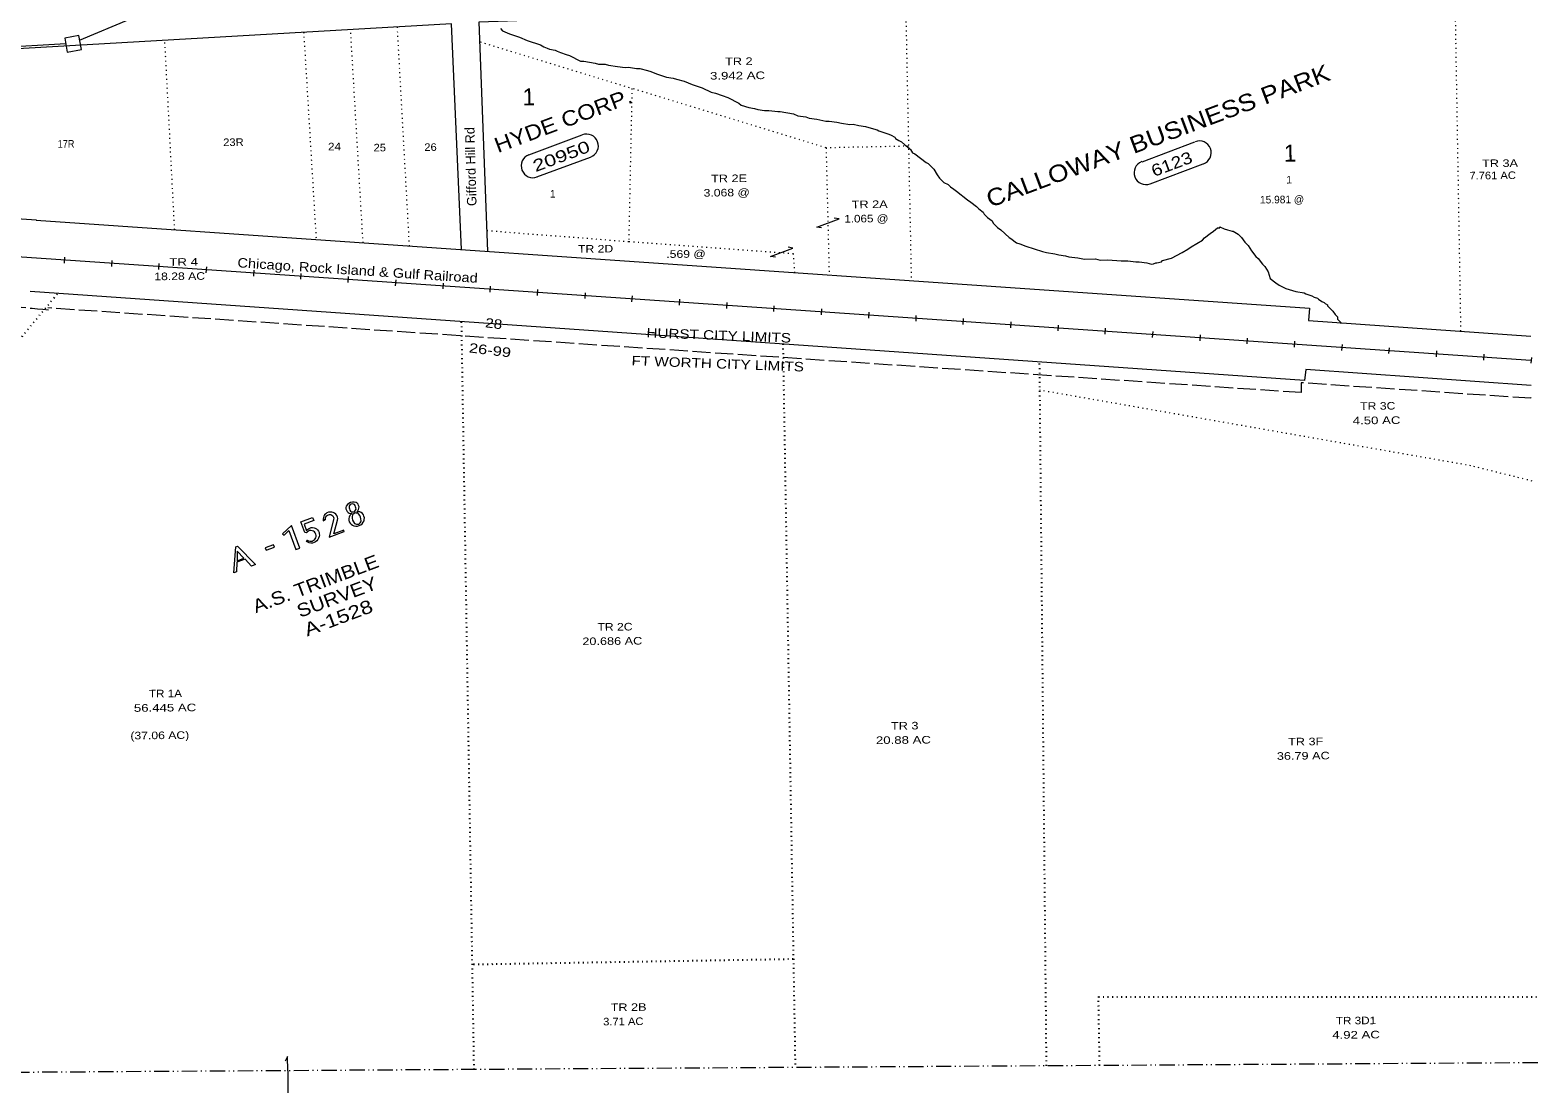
# Model space of a CAD drawing. Extents: x 2356373 to 2371954, y 6966197 to 6989612.
# Drawn here: x 2368762 to 2371940, y 6978330 to 6980551 of the extents above; entities that cross this region are included whole.
import ezdxf

# ---------------------------------------------------------------- set-up
doc = ezdxf.new("R2010")
doc.units = 0
doc.header["$LTSCALE"] = 6.4
for name, pattern in [('DASH_DOUBLE_DOT', [9.2, 5, -1.2, 0.3, -1.2, 0.3, -1.2]), ('DOTTED', [1.5, 0.3, -1.2]), ('LONG_DASHED', [7.5, 6, -1.5])]:
    doc.linetypes.add(name, pattern=pattern)
for name, color, linetype in [('10', 7, 'Continuous'), ('11', 7, 'Continuous'), ('18', 7, 'Continuous'), ('20', 7, 'Continuous'), ('22', 7, 'Continuous'), ('26', 7, 'Continuous')]:
    doc.layers.add(name, color=color, linetype=linetype)
for name, color, linetype, lineweight in [('12', 7, 'Continuous', 13), ('13', 7, 'Continuous', 13), ('15', 7, 'Continuous', 13), ('16', 7, 'DOTTED', 13), ('17', 7, 'Continuous', 13), ('19', 7, 'Continuous', 13), ('27', 7, 'LONG_DASHED', 13), ('30', 7, 'Continuous', 13), ('5', 7, 'DOTTED', 13), ('6', 7, 'DOTTED', 13), ('60', 7, 'DOTTED', 25), ('7', 7, 'Continuous', 13), ('8', 7, 'Continuous', 13)]:
    doc.layers.add(name, color=color, linetype=linetype, lineweight=lineweight)

msp = doc.modelspace()

# ---------------------------------------------------------------- linework, layer by layer
at = {"layer": '13'}
msp.add_line((2369304.625, 6978357.84), (2369305.815, 6978236.683), dxfattribs=at)
for points in [[(2370429.872, 6980134.321), (2370419.857, 6980136.02), (2370466.672, 6980153.577), (2370456.659, 6980155.178)], [(2370332.504, 6980072.581), (2370322.491, 6980074.181), (2370369.306, 6980091.737), (2370359.292, 6980093.437)], [(2369304.625, 6978357.84), (2369304.331, 6978387.728), (2369299.432, 6978377.683)]]:
    msp.add_lwpolyline(points, dxfattribs=at)
at = {"layer": '15', "linetype": 'DASH_DOUBLE_DOT'}
msp.add_line((2371939.757, 6978374.623), (2368123.015, 6978350.331), dxfattribs=at)
at = {"layer": '15'}
for points in [[(2369726.546, 6980084.723), (2369707.796, 6980568.709), (2370225.479, 6980586.991), (2371917.951, 6980594.717)], [(2369670.524, 6980088.572), (2369649.85, 6980564.841), (2367466.67, 6980438.925)], [(2368774.155, 6980150.448), (2371458.259, 6979965.169), (2371456.512, 6979939.357), (2371924.713, 6979906.369)], [(2371925.733, 6979802.406), (2371450.527, 6979836.227), (2371447.758, 6979812.806), (2368761.633, 6980000.365)]]:
    msp.add_lwpolyline(points, dxfattribs=at)
msp.add_arc((2368276.401, 6973930.218), 6240.133, 85.42076, 91.53776, dxfattribs=at)
at = {"layer": '16'}
for p, q in [((2371777.648, 6979916.82), (2371765.999, 6980594.025)), ((2370607.359, 6980588.743), (2370618.914, 6980023.106))]:
    msp.add_line(p, q, dxfattribs=at)
msp.add_lwpolyline([(2369710.211, 6980526.545), (2370030.09, 6980428.314), (2370023.267, 6980105.032), (2369725.121, 6980128.098)], dxfattribs=at)
at = {"layer": '17'}
for p, q in [((2369812.521, 6980288.514), (2369925.077, 6980330.609)), ((2371105.319, 6980273.92), (2371216.876, 6980316.104)), ((2369829.976, 6980241.698), (2369942.534, 6980283.793)), ((2371122.774, 6980227.202), (2371234.331, 6980269.288))]:
    msp.add_line(p, q, dxfattribs=at)
for points in [[(2369465.784, 6979520.022), (2369466.252, 6979523.275), (2369465.22, 6979526.514), (2369464.191, 6979529.503), (2369462.167, 6979532.083), (2369459.646, 6979534.158), (2369456.634, 6979535.577), (2369453.128, 6979536.243), (2369450.129, 6979536.214), (2369452.109, 6979538.182), (2369453.585, 6979540.597), (2369454.557, 6979543.405), (2369455.029, 6979546.309), (2369454.001, 6979549.148), (2369452.977, 6979551.737), (2369450.954, 6979553.916), (2369448.441, 6979555.491), (2369444.433, 6979556.352), (2369440.934, 6979556.268), (2369436.945, 6979555.329), (2369433.463, 6979553.546), (2369430.49, 6979551.016), (2369428.021, 6979547.844), (2369427.049, 6979545.034), (2369427.078, 6979542.036), (2369428.106, 6979539.197), (2369429.631, 6979536.613), (2369431.65, 6979534.533), (2369434.164, 6979533.057), (2369437.169, 6979532.388), (2369440.168, 6979532.467), (2369437.19, 6979530.438), (2369435.216, 6979527.819), (2369433.747, 6979524.756), (2369433.278, 6979521.502), (2369433.311, 6979518.153), (2369434.342, 6979514.914), (2369435.871, 6979511.98), (2369437.895, 6979509.551), (2369440.912, 6979507.68), (2369443.923, 6979506.56), (2369443.923, 6979506.56), (2369447.927, 6979505.799), (2369451.427, 6979505.885), (2369454.917, 6979506.819), (2369458.399, 6979508.502), (2369461.375, 6979510.931), (2369463.844, 6979513.905), (2369465.316, 6979516.818), (2369465.784, 6979520.022)], [(2369448.576, 6979541.747), (2369448.05, 6979544.292), (2369447.527, 6979546.735), (2369446.505, 6979549.024), (2369444.985, 6979551.109), (2369442.973, 6979552.339), (2369440.468, 6979552.764), (2369437.973, 6979552.339), (2369435.986, 6979551.121), (2369434.506, 6979549.206), (2369434.027, 6979546.953), (2369434.053, 6979544.404), (2369434.578, 6979541.96), (2369435.599, 6979539.67), (2369437.119, 6979537.586), (2369439.133, 6979536.205), (2369441.637, 6979535.681), (2369444.132, 6979536.106), (2369446.119, 6979537.425), (2369447.599, 6979539.388), (2369448.576, 6979541.747)], [(2369332.37, 6979514.912), (2369356.773, 6979524.199), (2369359.337, 6979517.527), (2369338.918, 6979509.778), (2369344.052, 6979496.133), (2369346.028, 6979498.501), (2369348.008, 6979500.37), (2369350.994, 6979501.749), (2369353.986, 6979502.578), (2369356.984, 6979502.807), (2369359.987, 6979502.387), (2369362.494, 6979501.412), (2369365.508, 6979499.892), (2369367.529, 6979497.812), (2369369.551, 6979495.383), (2369370.579, 6979492.643), (2369371.107, 6979489.7), (2369371.138, 6979486.651), (2369370.666, 6979483.647), (2369369.7, 6979480.338), (2369368.23, 6979477.325), (2369365.755, 6979474.701), (2369363.278, 6979472.576), (2369360.293, 6979471.048), (2369356.804, 6979470.164), (2369353.305, 6979469.98), (2369349.802, 6979470.446), (2369346.791, 6979471.665), (2369343.774, 6979473.485), (2369346.245, 6979476.309), (2369348.258, 6979474.979), (2369350.765, 6979474.155), (2369353.267, 6979473.929), (2369355.763, 6979474.353), (2369358.252, 6979475.278), (2369360.736, 6979476.751), (2369362.219, 6979478.666), (2369363.696, 6979480.929), (2369364.17, 6979483.584), (2369364.641, 6979486.338), (2369363.617, 6979488.977), (2369362.592, 6979491.415), (2369361.073, 6979493.5), (2369358.557, 6979495.125), (2369356.048, 6979496.149), (2369353.545, 6979496.575), (2369350.548, 6979496.296), (2369348.058, 6979495.373), (2369346.073, 6979493.902), (2369344.093, 6979491.883), (2369340.59, 6979492.2), (2369332.37, 6979514.912)], [(2369407.721, 6979528.098), (2369405.694, 6979530.879), (2369403.172, 6979533.004), (2369400.159, 6979534.522), (2369397.152, 6979535.343), (2369393.65, 6979535.508), (2369390.157, 6979534.976), (2369387.171, 6979533.745), (2369384.688, 6979531.922), (2369382.213, 6979529.599), (2369380.741, 6979526.785), (2369379.771, 6979523.676), (2369379.303, 6979520.472), (2369379.334, 6979517.173), (2369383.799, 6979520.766), (2369384.276, 6979523.121), (2369384.753, 6979525.374), (2369386.235, 6979527.287), (2369388.219, 6979528.758), (2369390.209, 6979529.777), (2369392.705, 6979530.151), (2369395.204, 6979529.976), (2369397.714, 6979529), (2369399.73, 6979527.27), (2369401.254, 6979524.987), (2369401.778, 6979522.343), (2369401.305, 6979519.689), (2369392.169, 6979482.758), (2369423.546, 6979494.514), (2369422.521, 6979497.153), (2369401.604, 6979489.2), (2369409.316, 6979518.167), (2369409.783, 6979521.621), (2369409.25, 6979524.964), (2369407.721, 6979528.098)], [(2369458.779, 6979520.803), (2369457.741, 6979524.643), (2369456.205, 6979528.275), (2369453.673, 6979531.599), (2369452.163, 6979532.735), (2369449.658, 6979533.359), (2369447.657, 6979533.439), (2369445.662, 6979532.971), (2369443.674, 6979531.901), (2369441.689, 6979530.383), (2369440.707, 6979528.523), (2369440.228, 6979526.369), (2369440.268, 6979522.372), (2369441.306, 6979518.432), (2369442.842, 6979514.798), (2369445.372, 6979511.574), (2369447.383, 6979510.393), (2369449.39, 6979509.714), (2369451.391, 6979509.632), (2369453.885, 6979510.108), (2369455.874, 6979511.177), (2369457.358, 6979512.741), (2369458.838, 6979514.655), (2369459.317, 6979516.809), (2369458.779, 6979520.803)], [(2369312.454, 6979506.818), (2369293.626, 6979489.789), (2369296.658, 6979486.419), (2369306.558, 6979496.363), (2369321.948, 6979456.326), (2369329.916, 6979459.403), (2369312.454, 6979506.818)], [(2369198.411, 6979463.411), (2369236.784, 6979424.547), (2369228.318, 6979421.314), (2369214.676, 6979435.978), (2369197.245, 6979429.557), (2369196.442, 6979409.456), (2369190.965, 6979407.352), (2369194.925, 6979462.126), (2369198.411, 6979463.411)], [(2369212.155, 6979438.202), (2369198.012, 6979453.208), (2369197.714, 6979432.661), (2369212.155, 6979438.202)], [(2369276.411, 6979461.327), (2369274.358, 6979466.655), (2369256.928, 6979460.185), (2369258.979, 6979454.858), (2369276.411, 6979461.327)]]:
    msp.add_lwpolyline(points, close=True, dxfattribs=at)
for points in [[(2369383.799, 6979520.766), (2369379.334, 6979517.173), (2369383.799, 6979520.766)], [(2369346.245, 6979476.309), (2369343.774, 6979473.485), (2369346.245, 6979476.309)]]:
    msp.add_lwpolyline(points, dxfattribs=at)
for centre, start, end in [((2369934.305, 6980307.205), 290.56276, 110.56276), ((2371226.103, 6980292.701), 290.56276, 110.56276), ((2369821.749, 6980265.11), 110.56276, 290.56276), ((2371113.546, 6980250.606), 110.56276, 290.56276)]:
    msp.add_arc(centre, 24.992, start, end, dxfattribs=at)
at = {"layer": '27', "linetype": 'Continuous'}
msp.add_line((2371925.994, 6979775.916), (2371924.993, 6979776.005), dxfattribs=at)
at = {"layer": '27'}
msp.add_lwpolyline([(2371925.001, 6979775.205), (2371440.809, 6979807.839), (2371441.012, 6979787.146), (2368798.965, 6979965.642)], dxfattribs=at)
msp.add_arc((2368278.864, 6974595.465), 5390.901, 84.45176, 115.76276, dxfattribs=at)
at = {"layer": '30'}
for p, q in [((2368833.903, 6980072.656), (2368833.025, 6980060.151)), ((2368833.903, 6980072.656), (2368833.025, 6980060.151)), ((2368933.943, 6980065.84), (2368933.066, 6980053.336)), ((2369032.984, 6980059.016), (2369032.107, 6980046.511)), ((2369133.025, 6980052.2), (2369132.148, 6980039.695)), ((2369233.065, 6980045.385), (2369232.188, 6980032.879)), ((2369332.106, 6980038.56), (2369331.228, 6980026.054)), ((2369432.145, 6980031.745), (2369431.269, 6980019.239)), ((2369532.185, 6980024.929), (2369531.308, 6980012.423)), ((2369632.226, 6980018.114), (2369631.348, 6980005.709)), ((2369731.266, 6980011.289), (2369730.388, 6979998.884)), ((2369831.306, 6980004.474), (2369830.429, 6979992.069)), ((2369931.347, 6979997.658), (2369930.469, 6979985.253)), ((2370030.388, 6979990.833), (2370029.51, 6979978.43)), ((2370130.428, 6979984.018), (2370129.551, 6979971.612)), ((2370230.468, 6979977.202), (2370229.591, 6979964.797)), ((2370329.508, 6979970.378), (2370328.63, 6979957.972)), ((2370429.548, 6979963.663), (2370428.671, 6979951.158)), ((2370529.587, 6979956.846), (2370528.712, 6979944.342)), ((2370628.628, 6979950.021), (2370628.752, 6979937.526)), ((2370728.669, 6979943.207), (2370727.792, 6979930.701)), ((2370828.709, 6979936.391), (2370827.833, 6979923.886)), ((2370928.749, 6979929.576), (2370927.874, 6979917.071)), ((2371027.79, 6979922.751), (2371026.913, 6979910.246)), ((2371127.831, 6979915.937), (2371126.953, 6979903.43)), ((2371227.87, 6979909.12), (2371226.995, 6979896.615)), ((2371326.911, 6979902.295), (2371326.035, 6979889.79)), ((2371426.951, 6979895.479), (2371426.073, 6979882.975)), ((2371526.991, 6979888.665), (2371526.115, 6979876.16)), ((2371626.033, 6979881.839), (2371625.154, 6979869.434)), ((2371726.073, 6979875.024), (2371725.196, 6979862.619)), ((2371826.114, 6979868.209), (2371825.236, 6979855.804)), ((2371926.153, 6979861.394), (2371925.275, 6979848.988))]:
    msp.add_line(p, q, dxfattribs=at)
at = {"layer": '5'}
msp.add_line((2370439.21, 6980303.066), (2370030.09, 6980428.314), dxfattribs=at)
at = {"layer": '5', "linetype": 'Continuous'}
msp.add_line((2371925.215, 6979855.186), (2368586.865, 6980083.225), dxfattribs=at)
at = {"layer": '5'}
for points in [[(2370613.129, 6980306.574), (2370439.21, 6980303.066), (2370445.843, 6980035.004)], [(2370373.813, 6980039.995), (2370370.421, 6980079.851), (2370023.267, 6980105.032)], [(2371927.715, 6979600.678), (2371798.43, 6979633.1), (2370890.11, 6979792.232)]]:
    msp.add_lwpolyline(points, dxfattribs=at)
at = {"layer": '6'}
for p, q in [((2369534.946, 6980558.215), (2369560.478, 6980096.189)), ((2369066.276, 6980130.223), (2369045.353, 6980530.011)), ((2369338.109, 6980546.884), (2369364.398, 6980109.659)), ((2369463.439, 6980102.833), (2369437.027, 6980552.553))]:
    msp.add_line(p, q, dxfattribs=at)
at = {"layer": '60'}
for p, q in [((2369697.495, 6978360.298), (2369671.013, 6979936.917)), ((2370348.298, 6979889.584), (2370374.273, 6978364.646)), ((2370904.098, 6978368.051), (2370889.524, 6979851.811)), ((2370370.032, 6978592.843), (2369693.325, 6978581.397))]:
    msp.add_line(p, q, dxfattribs=at)
for points in [[(2367075.265, 6978963.973), (2368694.553, 6978992.475), (2368683.317, 6979831.041), (2368819.657, 6979996.337)], [(2371016.062, 6978368.751), (2371013.64, 6978513.587), (2371938.388, 6978513.873)]]:
    msp.add_lwpolyline(points, dxfattribs=at)
at = {"layer": '7'}
for p, q in [((2368865.403, 6980529.844), (2369332.35, 6980725.98)), ((2368233.981, 6980488.15), (2368836.481, 6980522.761))]:
    msp.add_line(p, q, dxfattribs=at)
msp.add_lwpolyline([(2368839.654, 6980504.897), (2368869.591, 6980510.489), (2368864.304, 6980539.93), (2368834.366, 6980534.438)], close=True, dxfattribs=at)
at = {"layer": '8'}
for points in [[(2369752.922, 6980554.757), (2369756.966, 6980550.098), (2369772.03, 6980543.248), (2369793.092, 6980536.356), (2369809.154, 6980529.515), (2369837.236, 6980520.395), (2369844.279, 6980515.766), (2369851.301, 6980513.434), (2369856.322, 6980511.184), (2369868.34, 6980508.903), (2369872.363, 6980506.644), (2369879.383, 6980504.312), (2369891.425, 6980499.732), (2369898.445, 6980497.502), (2369921.553, 6980485.931), (2369928.549, 6980486.001), (2369952.587, 6980481.538), (2369959.607, 6980479.308), (2369973.603, 6980479.445), (2369980.623, 6980477.114), (2369999.639, 6980474.903), (2370015.656, 6980472.76), (2370022.655, 6980472.829), (2370039.672, 6980470.596), (2370046.669, 6980470.665), (2370062.71, 6980466.124), (2370069.729, 6980463.794), (2370081.773, 6980459.213), (2370102.833, 6980452.421), (2370116.853, 6980450.161), (2370123.872, 6980447.929), (2370139.913, 6980443.389), (2370156.976, 6980436.458), (2370178.036, 6980429.667), (2370197.122, 6980420.457), (2370206.143, 6980418.147), (2370220.183, 6980413.586), (2370232.225, 6980409.005), (2370255.333, 6980397.535), (2370260.377, 6980392.886), (2370276.415, 6980388.344), (2370288.436, 6980386.063), (2370295.455, 6980383.833), (2370309.474, 6980381.571), (2370318.47, 6980381.659), (2370337.487, 6980379.447), (2370342.486, 6980379.495), (2370370.522, 6980375.073), (2370379.564, 6980370.462), (2370396.581, 6980368.231), (2370403.602, 6980365.999), (2370419.62, 6980363.759), (2370438.658, 6980359.246), (2370445.657, 6980359.315), (2370461.674, 6980357.074), (2370471.692, 6980354.872), (2370489.709, 6980352.649), (2370496.707, 6980352.717), (2370508.727, 6980350.538), (2370522.744, 6980348.275), (2370529.765, 6980345.945), (2370546.805, 6980341.414), (2370550.827, 6980339.153), (2370562.868, 6980334.574), (2370571.889, 6980332.263), (2370576.91, 6980330.011), (2370583.953, 6980325.383), (2370585.974, 6980323.102), (2370593.018, 6980318.474), (2370598.04, 6980316.123), (2370605.106, 6980309.195), (2370614.173, 6980302.187), (2370617.195, 6980299.916), (2370621.262, 6980292.859), (2370626.284, 6980290.608), (2370650.46, 6980272.05), (2370654.481, 6980269.791), (2370666.591, 6980258.112), (2370673.704, 6980246.486), (2370678.771, 6980239.538), (2370687.86, 6980230.23), (2370696.903, 6980225.618), (2370701.948, 6980220.97), (2370708.991, 6980216.341), (2370714.035, 6980211.692), (2370737.21, 6980193.223), (2370744.254, 6980188.595), (2370756.343, 6980179.315), (2370761.386, 6980174.666), (2370770.452, 6980167.657), (2370772.498, 6980162.979), (2370779.564, 6980156.051), (2370789.629, 6980149.15), (2370791.675, 6980144.472), (2370800.765, 6980135.163), (2370807.808, 6980130.535), (2370824.962, 6980114.306), (2370828.984, 6980111.948)], [(2370828.984, 6980111.948), (2370841.071, 6980102.669), (2370848.093, 6980100.438), (2370860.133, 6980095.858), (2370895.237, 6980084.405), (2370904.258, 6980082.195), (2370921.273, 6980079.963), (2370930.293, 6980077.751), (2370944.311, 6980075.489), (2370951.332, 6980073.259), (2370970.348, 6980071.046), (2370984.367, 6980068.787), (2371007.359, 6980069.01), (2371017.379, 6980066.71), (2371033.373, 6980066.867), (2371061.387, 6980064.744), (2371075.38, 6980064.881), (2371092.399, 6980062.748), (2371099.395, 6980062.817), (2371115.414, 6980060.575), (2371125.432, 6980058.275), (2371129.432, 6980058.314), (2371134.406, 6980060.762), (2371136.406, 6980060.782), (2371146.38, 6980063.179), (2371148.355, 6980065.498), (2371167.303, 6980070.382), (2371190.179, 6980082.304), (2371202.107, 6980089.419), (2371209.057, 6980094.186), (2371232.911, 6980108.417), (2371236.864, 6980113.154), (2371248.768, 6980122.669), (2371255.72, 6980127.336), (2371264.647, 6980134.521), (2371269.645, 6980134.572), (2371269.622, 6980136.869), (2371278.665, 6980132.259), (2371285.685, 6980130.029), (2371295.706, 6980127.729), (2371297.705, 6980127.748), (2371307.77, 6980120.85), (2371314.837, 6980113.82), (2371321.925, 6980104.492), (2371328.992, 6980097.563), (2371336.105, 6980085.936), (2371345.218, 6980074.23), (2371350.261, 6980069.679), (2371359.373, 6980057.973), (2371364.417, 6980053.324), (2371371.53, 6980041.696), (2371375.668, 6980027.641), (2371387.753, 6980018.462), (2371394.798, 6980013.833), (2371408.862, 6980006.873), (2371429.923, 6980000.08), (2371446.941, 6979997.849), (2371450.962, 6979995.589), (2371463.004, 6979991.008), (2371468.026, 6979988.658), (2371475.046, 6979986.329), (2371477.069, 6979984.05), (2371484.112, 6979979.419), (2371489.131, 6979977.169), (2371491.156, 6979974.79), (2371496.177, 6979972.539), (2371496.199, 6979970.141), (2371507.311, 6979958.552), (2371512.377, 6979951.604), (2371517.421, 6979946.955), (2371517.467, 6979942.258), (2371524.536, 6979935.227), (2371524.558, 6979932.928), (2371524.536, 6979935.227)]]:
    msp.add_lwpolyline(points, dxfattribs=at)

# ---------------------------------------------------------------- texts
at = {"layer": '10'}
for s, width, p in [('TR 2', 1.25, (2370226.557, 6980477.23)), ('TR 3A', 1.25, (2371822.241, 6980262.366)), ('TR 2E', 1.25, (2370196.99, 6980230.407)), ('TR 2A', 1.25, (2370493.447, 6980175.733)), ('TR 2D', 1.2, (2369916.523, 6980081.99)), ('TR 4', 1.3, (2369055.025, 6980054.334)), ('TR 3C', 1.2, (2371565.336, 6979750.778)), ('TR 2C', 1.2, (2369957.339, 6979285.204)), ('TR 1A', 1.15, (2369011.972, 6979144.654)), ('TR 3', 1.25, (2370576.222, 6979076.74)), ('TR 3F', 1.25, (2371413.328, 6979043.373)), ('TR 2B', 1.25, (2369985.209, 6978483.492)), ('TR 3D1', 1.15, (2371514.079, 6978455.221))]:
    msp.add_text(s, height=15.99, rotation=0.563, dxfattribs=dict(at, width=width)).set_placement(p)
at = {"layer": '11'}
for s, width, p in [('3.942 AC', 1.3, (2370194.864, 6980446.926)), ('7.761 AC', 1.1, (2371795.503, 6980236.51)), ('3.068 @', 1.2, (2370181.289, 6980200.26)), ('1.065 @', 1.15, (2370477.747, 6980145.587)), ('.569 @', 1.2, (2370102.581, 6980071.021)), ('18.28 AC', 1.2, (2369023.331, 6980024.031)), ('4.50 AC', 1.3, (2371549.64, 6979720.232)), ('20.686 AC', 1.25, (2369925.646, 6979254.9)), ('56.445 AC', 1.3, (2368980.28, 6979114.35)), ('(37.06 AC)', 1.2, (2368972.852, 6979056.193)), ('20.88 AC', 1.3, (2370544.529, 6979046.436)), ('36.79 AC', 1.25, (2371389.63, 6979013.148)), ('3.71 AC', 1.1, (2369969.508, 6978453.346)), ('4.92 AC', 1.3, (2371506.376, 6978425.153))]:
    msp.add_text(s, height=15.99, rotation=0.563, dxfattribs=dict(at, width=width)).set_placement(p)
msp.add_text('15.981 @', height=15.99, rotation=0.563, dxfattribs=at).set_placement((2371354.12, 6980185.787))
at = {"layer": '12'}
for s, width, p in [('17R', 0.9, (2368819.641, 6980303.354)), ('23R', 1.1, (2369168.514, 6980306.781)), ('24', 1.15, (2369389.544, 6980297.755)), ('25', 1.1, (2369485.54, 6980295.499)), ('26', 1.1, (2369592.5, 6980296.549))]:
    msp.add_text(s, height=15.99, rotation=0.563, dxfattribs=dict(at, width=width)).set_placement(p)
for p in [(2371409.69, 6980227.923), (2369857.396, 6980198.279)]:
    msp.add_text('1', height=15.99, rotation=0.563, dxfattribs=at).set_placement(p)
at = {"layer": '17'}
for s, width, p in [('20950', 1.35, (2369826.876, 6980251.864)), ('6123', 1.2, (2371130.629, 6980241.675))]:
    msp.add_text(s, height=24.99, rotation=20.563, dxfattribs=dict(at, width=width)).set_placement(p)
at = {"layer": '18', "width": 1.15}
for s, height, p in [('CALLOWAY BUSINESS PARK', 35.99, (2370785.361, 6980176.601)), ('HYDE CORP.', 31.99, (2369747.506, 6980291.874))]:
    msp.add_text(s, height=height, rotation=20.563, dxfattribs=at).set_placement(p)
at = {"layer": '19'}
msp.add_text('Gifford Hill Rd', height=19.99, rotation=91.563, dxfattribs=at).set_placement((2369702.609, 6980180.763))
at = {"layer": '19', "width": 1.15}
msp.add_text('Chicago, Rock Island & Gulf Railroad', height=19.99, rotation=356.273, dxfattribs=at).set_placement((2369198.014, 6980051.439))
at = {"layer": '20'}
for s, width, p in [('A.S. TRIMBLE', 1.15, (2369237.17, 6979322.018)), ('SURVEY', 1.15, (2369330.243, 6979312.236)), ('A-1528', 1.25, (2369345.624, 6979272.896))]:
    msp.add_text(s, height=27.99, rotation=20.563, dxfattribs=dict(at, width=width)).set_placement(p)
at = {"layer": '22'}
for p in [(2369799.502, 6980392.558), (2371404.24, 6980273.855)]:
    msp.add_text('1', height=35.99, rotation=0.563, dxfattribs=at).set_placement(p)
at = {"layer": '26'}
for s, rotation, width, p in [('28', 352.973, 1.2, (2369719.947, 6979924.99)), ('HURST CITY LIMITS', 357.903, 1.2, (2370060.482, 6979903.636)), ('26-99', 352.973, 1.3, (2369685.67, 6979872.105)), ('FT WORTH CITY LIMITS', 357.903, 1.2, (2370029.069, 6979844.843))]:
    msp.add_text(s, height=19.99, rotation=rotation, dxfattribs=dict(at, width=width)).set_placement(p)

doc.saveas('drawing.dxf')
